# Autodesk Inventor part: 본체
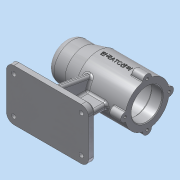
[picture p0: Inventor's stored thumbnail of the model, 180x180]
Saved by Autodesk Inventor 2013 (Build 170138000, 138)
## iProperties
Created: 2019-07
Part Number: 본체
Material: 알루미늄 6061
Document SubType Name: Modeling
Designer: Administrator
Density: 2.71 g/cm^3
Mass: 783.637 g
Surface Area: 620.522 cm^2
Volume: 289.165 cm^3
Author: Administrator
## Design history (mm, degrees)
sketch "스케치1"
  geometry: L1 (17.653, 2.338)-(42.653, 2.338); L2 (17.653, -22.662)-(17.653, 2.338); L3 (62.653, 7.338)-(129.653, 7.338); L4 (129.653, 7.338)-(129.653, -1.662); L5 (17.653, -22.662)-(60.653, -22.662); L6 (42.653, 2.338)-(62.653, 7.338); L7 (114.653, -1.662)-(129.653, -1.662); L8 (60.653, 1.338)-(114.653, 1.338); L9 (114.653, 1.338)-(114.653, -1.662); L10 (60.653, -22.662)-(60.653, 1.338); 2 further points
  constraints: 20 end point, 4 horizontal, 2 perpendicular, 1 parallel, 1 vertical alignment
  dimensions: "d5" = 25 distance of L2.start L1.start; "d6" = 25 distance from line of L1.end L2; "d7" = 45 distance from line of L3.start L2; "d8" = 112 distance between parallel lines of L2 L4; "d9" = 30 distance of L3.end point (129.653, -22.662); "d22" = 54 distance of L8.start L8.end; "d23" = 24 distance of L5.end L8.start; "d24" = 21 distance between parallel lines of L5 L7; "d25" = 15 distance of L7.start L4.end
revolve "회전1" sketch "스케치1" stored, may be unused: angle "d10" = 90 deg
fillet "모깎기1" dims "d11" = 10
fillet "모깎기2" dims "d26" = 3
hole "구멍1" diameter "d29" = 35; stored, may be unused: countersink angle "d33" = 90 deg, drill point angle "d35" = 0 deg; dims "d30" = 6, "d31" = 42, "d32" = 12, "d34" = 30, "d36" = 10, "d37" = 10
fillet "모깎기3" dims "d38" = 0.3
sketch "스케치2"
  geometry: C1 r 17.2 at (0, 0) reference; 1 further point
hole "구멍2" sketch "스케치2" at (0, 0) diameter "d39" = 21; stored, may be unused: countersink angle "d43" = 90 deg, drill point angle "d45" = 0 deg; dims "d40" = 6, "d41" = 32, "d42" = 4, "d44" = 7
fillet "모깎기4" dims "d46" = 0.3
fillet "모깎기5" dims "d47" = 3
sketch "스케치3"
  geometry: L1 (129.653, -52.662)-(129.653, 7.338) reference; L2 (129.653, -102.662)-(17.653, -102.662); L3 (17.653, -102.662)-(17.653, -92.662); L4 (17.653, -92.662)-(129.653, -92.662); L5 (129.653, -92.662)-(129.653, -102.662); L6 (27.653, 2.338)-(42.653, 2.338) reference; L7 (42.653, 2.338)-(62.653, 7.338) reference; L8 (62.653, 7.338)-(129.653, 7.338) reference; L9 (129.653, 7.338)-(129.653, -1.662) reference; L10 (129.653, -1.662)-(114.653, -1.662) reference; L11 (111.653, 1.338)-(63.653, 1.338) reference; L12 (60.653, -1.662)-(48.953, -1.662) reference; L13 (48.653, -1.962)-(48.653, -5.162) reference; L14 (48.653, -5.162)-(30.953, -5.162) reference; L15 (30.653, -5.462)-(30.653, -6.662) reference; L16 (30.653, -6.662)-(26.953, -6.662) reference; L17 (26.653, -6.962)-(26.653, -12.162) reference; L18 (23.653, -15.162)-(23.653, -30.162) reference; L19 (26.653, -33.162)-(26.653, -38.362) reference; L20 (26.953, -38.662)-(30.653, -38.662) reference; L21 (30.653, -38.662)-(30.653, -39.862) reference; L22 (30.953, -40.162)-(48.653, -40.162) reference; L23 (48.653, -40.162)-(48.653, -43.362) reference; L24 (48.953, -43.662)-(60.653, -43.662) reference; L25 (63.653, -46.662)-(111.653, -46.662) reference; L26 (114.653, -43.662)-(129.653, -43.662) reference; L27 (129.653, -43.662)-(129.653, -52.662) reference; L28 (129.653, -52.662)-(62.653, -52.662) reference; L29 (62.653, -52.662)-(42.653, -47.662) reference; L30 (42.653, -47.662)-(27.653, -47.662) reference; L31 (17.653, -37.662)-(17.653, -7.662) reference; L32 (17.653, -37.662)-(17.653, -7.662) reference; A1 r 10 centre (27.653, -7.662) between (27.653, 2.338) and (17.653, -7.662) reference; A2 r 3 centre (111.653, -1.662) between (114.653, -1.662) and (111.653, 1.338) reference; A3 r 3 centre (63.653, -1.662) between (63.653, 1.338) and (60.653, -1.662) reference; A4 r 0.3 centre (48.953, -1.962) between (48.953, -1.662) and (48.653, -1.962) reference; A5 r 0.3 centre (30.953, -5.462) between (30.953, -5.162) and (30.653, -5.462) reference; A6 r 0.3 centre (26.953, -6.962) between (26.953, -6.662) and (26.653, -6.962) reference; A7 r 3 centre (26.653, -15.162) between (26.653, -12.162) and (23.653, -15.162) reference; A8 r 3 centre (26.653, -30.162) between (23.653, -30.162) and (26.653, -33.162) reference; A9 r 0.3 centre (26.953, -38.362) between (26.653, -38.362) and (26.953, -38.662) reference; A10 r 0.3 centre (30.953, -39.862) between (30.653, -39.862) and (30.953, -40.162) reference; A11 r 0.3 centre (48.953, -43.362) between (48.653, -43.362) and (48.953, -43.662) reference; A12 r 3 centre (63.653, -43.662) between (60.653, -43.662) and (63.653, -46.662) reference; A13 r 3 centre (111.653, -43.662) between (111.653, -46.662) and (114.653, -43.662) reference; A14 r 10 centre (27.653, -37.662) between (17.653, -37.662) and (27.653, -47.662) reference; 2 further points
  constraints: 8 end point, 2 parallel, 1 horizontal, 1 midpoint, 1 perpendicular
  dimensions: "d49" = 112 distance of L3.end L4.end; "d50" = 10 distance of L2.end L3.end; "d51" = 80 distance from line of point (17.653, -22.662) L2
extrude "돌출1" join sketch "스케치3" distance "d52" = 35; taper "d54" = 0 deg; dims "d53" = 35, "d55" = 0
fillet "모깎기6" dims "d56" = 10
hole "구멍3" diameter "d59" = 6; stored, may be unused: countersink angle "d63" = 90 deg, drill point angle "d65" = 0 deg; dims "d57" = 10, "d58" = 10, "d60" = 6, "d61" = 32, "d62" = 4, "d64" = 10
sketch "스케치4"
  geometry: C1 r 21 at (0, 0) reference; C2 r 6 at (0, 30); C3 r 6 at (-30, 0); C4 r 6 at (0, -30); C5 r 6 at (30, 0); 2 further points
  constraints: 4 centre point, 1 vertical alignment, 10 other
  dimensions: "d72" = 12 diameter of C2; "d75" = 360 deg dimension on C1.centre C2.centre (derived)
extrude "돌출2" join sketch "스케치4" distance "d77" = 16; taper "d78" = 0 deg
fillet "모깎기7" dims "d79" = 1
fillet "모깎기9" dims "d81" = 1
fillet "모깎기10" dims "d82" = 1
fillet "모깎기11" dims "d83" = 1
chamfer "모따기1" distance "d84" = 1; stored, may be unused: second distance "d85" = 2, angle "d86" = 45 deg
hole "구멍4" diameter "d89" = 3.459; stored, may be unused: countersink angle "d93" = 90 deg, drill point angle "d95" = 118 deg; dims "d87" = 10, "d88" = 10, "d90" = 8, "d91" = 32, "d92" = 4, "d94" = 11
node "작업 평면1"
sketch "스케치5"
  geometry: L1 (37.653, -92.662)-(104.653, -92.662); L2 (17.653, -102.662)-(17.653, -92.662) reference; L3 (129.653, -92.662)-(129.653, -102.662) reference; L4 (37.653, -92.662)-(123.327, -92.662); L5 (27.653, 2.338)-(42.653, 2.338) reference; L6 (42.653, 2.338)-(62.653, 7.338) reference; L7 (62.653, 7.338)-(112.653, 7.338) reference; L8 (113.653, 8.338)-(113.653, 12.338) reference; L9 (114.653, 13.338)-(129.653, 13.338) reference; L10 (129.653, 13.338)-(129.653, 9.068) reference; L11 (129.653, 9.068)-(118.653, 9.068) reference; L12 (118.653, 9.068)-(117.614, 7.338) reference; L13 (117.614, 7.338)-(118.653, 5.609) reference; L14 (118.653, 5.609)-(129.653, 5.609) reference; L15 (129.653, 5.609)-(129.653, -0.662) reference; L16 (129.653, -0.662)-(128.653, -1.662) reference; L17 (128.653, -1.662)-(114.653, -1.662) reference; L18 (111.653, 1.338)-(63.653, 1.338) reference; L19 (60.653, -1.662)-(48.953, -1.662) reference; L20 (48.653, -1.962)-(48.653, -5.162) reference; L21 (48.653, -5.162)-(30.953, -5.162) reference; L22 (30.653, -5.462)-(30.653, -6.662) reference; L23 (30.653, -6.662)-(26.953, -6.662) reference; L24 (26.653, -6.962)-(26.653, -12.162) reference; L25 (23.653, -15.162)-(23.653, -30.162) reference; L26 (26.653, -33.162)-(26.653, -38.362) reference; L27 (26.953, -38.662)-(30.653, -38.662) reference; L28 (30.653, -38.662)-(30.653, -39.862) reference; L29 (30.953, -40.162)-(48.653, -40.162) reference; L30 (48.653, -40.162)-(48.653, -43.362) reference; L31 (48.953, -43.662)-(60.653, -43.662) reference; L32 (63.653, -46.662)-(111.653, -46.662) reference; L33 (114.653, -43.662)-(128.653, -43.662) reference; L34 (128.653, -43.662)-(129.653, -44.662) reference; L35 (129.653, -44.662)-(129.653, -50.932) reference; L36 (129.653, -50.932)-(118.653, -50.932) reference; L37 (118.653, -50.932)-(117.614, -52.662) reference; L38 (117.614, -52.662)-(118.653, -54.391) reference; L39 (118.653, -54.391)-(129.653, -54.391) reference; L40 (129.653, -54.391)-(129.653, -58.662) reference; L41 (129.653, -58.662)-(114.653, -58.662) reference; L42 (113.653, -57.662)-(113.653, -53.662) reference; L43 (112.653, -52.662)-(62.653, -52.662) reference; L44 (62.653, -52.662)-(42.653, -47.662) reference; L45 (42.653, -47.662)-(27.653, -47.662) reference; L46 (17.653, -37.662)-(17.653, -7.662) reference; L47 (17.653, -102.662)-(17.653, -92.662) reference; L48 (17.653, -92.662)-(129.653, -92.662) reference; L49 (129.653, -92.662)-(129.653, -102.662) reference; L50 (129.653, -102.662)-(17.653, -102.662) reference; L51 (104.653, -92.662)-(104.653, -50.162); L52 (53.122, -50.162)-(104.653, -50.162); L53 (37.653, -92.662)-(53.122, -50.162); A1 r 10 centre (27.653, -7.662) between (27.653, 2.338) and (17.653, -7.662) reference; A2 r 1 centre (112.653, 8.338) between (112.653, 7.338) and (113.653, 8.338) reference; A3 r 1 centre (114.653, 12.338) between (114.653, 13.338) and (113.653, 12.338) reference; A4 r 3 centre (111.653, -1.662) between (114.653, -1.662) and (111.653, 1.338) reference; A5 r 3 centre (63.653, -1.662) between (63.653, 1.338) and (60.653, -1.662) reference; A6 r 0.3 centre (48.953, -1.962) between (48.953, -1.662) and (48.653, -1.962) reference; A7 r 0.3 centre (30.953, -5.462) between (30.953, -5.162) and (30.653, -5.462) reference; A8 r 0.3 centre (26.953, -6.962) between (26.953, -6.662) and (26.653, -6.962) reference; A9 r 3 centre (26.653, -15.162) between (26.653, -12.162) and (23.653, -15.162) reference; A10 r 3 centre (26.653, -30.162) between (23.653, -30.162) and (26.653, -33.162) reference; A11 r 0.3 centre (26.953, -38.362) between (26.653, -38.362) and (26.953, -38.662) reference; A12 r 0.3 centre (30.953, -39.862) between (30.653, -39.862) and (30.953, -40.162) reference; A13 r 0.3 centre (48.953, -43.362) between (48.653, -43.362) and (48.953, -43.662) reference; A14 r 3 centre (63.653, -43.662) between (60.653, -43.662) and (63.653, -46.662) reference; A15 r 3 centre (111.653, -43.662) between (111.653, -46.662) and (114.653, -43.662) reference; A16 r 1 centre (114.653, -57.662) between (113.653, -57.662) and (114.653, -58.662) reference; A17 r 1 centre (112.653, -53.662) between (113.653, -53.662) and (112.653, -52.662) reference; A18 r 10 centre (27.653, -37.662) between (17.653, -37.662) and (27.653, -47.662) reference; 1 further point
  constraints: 10 end point, 1 horizontal, 1 parallel, 1 perpendicular
  dimensions: "d104" = 20 distance from line of L1.start L2; "d105" = 25 distance from line of L3 L1.end; "d107" = 110 deg angle of L48 L53
extrude "돌출3" join sketch "스케치5" distance "d108" = 4; taper "d109" = 0 deg; dims "d110" = 4, "d111" = 0
fillet "모깎기12" dims "d112" = 3
node "작업 평면2"
sketch "스케치6"
  geometry: L1 (-53, 10)-(-44.654, 57.334); L2 (-53, 10)-(-16.134, 10); L3 (0, 10)-(62.345, 10); L4 (3, 10)-(-5.346, 57.334); L5 (3, 10)-(68.522, 10); L6 (-53, 10)-(3, 10); A1 r 30 centre (-25, 80) between (-44.654, 57.334) and (-5.346, 57.334); 1 further point
  constraints: 12 end point, 3 horizontal, 2 point on circle, 1 centre point
  dimensions: "d116" = 80 deg angle of L2 L1; "d118" = 100 deg angle of L5 L4
fillet "모깎기14" dims "d124" = 3
extrude "돌출5" join sketch "스케치6" stored distance "d125" = 8; taper "d126" = 0 deg
fillet "모깎기15" dims "d127" = 3
node "작업 평면3"
sketch "스케치7"
  geometry: L1 (33.5, 5.998)-(33.5, -5.998) reference; 3 further points
  constraints: 1 horizontal alignment, 1 midpoint, 1 other
  dimensions: "d128" = 42 distance from line of L1 point (-8.5, 0)
feature "엠보싱1" sketch "스케치7" dims "d5" = 25, "d6" = 25, "d7" = 45, "d8" = 112, "d9" = 30, "d22" = 54, "d23" = 24, "d24" = 21, "d25" = 15, "d30" = 6, "d129" = 0.5, "d130" = 0
chamfer "모따기2" distance "d131" = 3; stored, may be unused: second distance "d132" = 2, angle "d133" = 45 deg
node "솔리드1"
pattern_linear "직사각형 패턴1" dims "d68" = 50, "d71" = 92
pattern_circular "원형 패턴1" dims angle "d97" = 360 deg
node "절단 모서리 투영1"
node "절단 모서리 투영3"
other parameters: "d106" = 70 deg, "d117" = 100 deg
